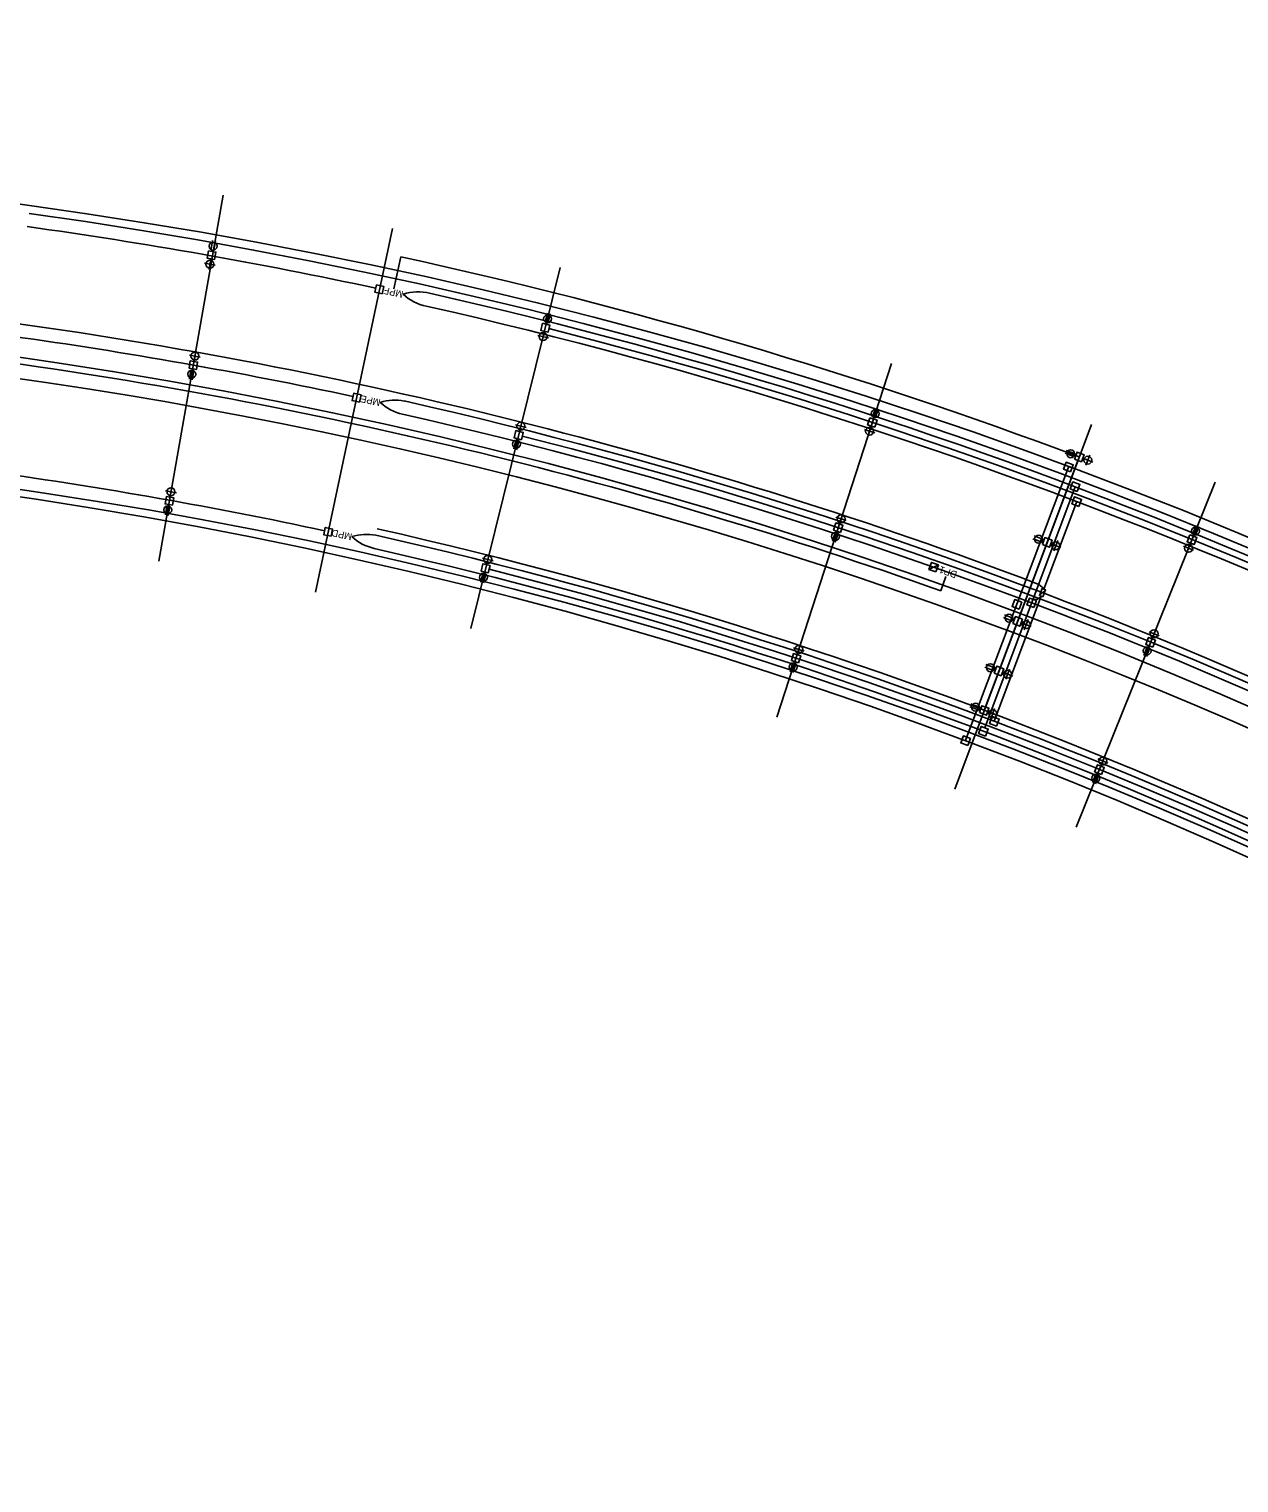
# Model space of a CAD drawing. Extents: x 928165 to 929015, y 635755 to 636543.
# Drawn here: x 928372.8 to 928555.1, y 636320.8 to 636539.8 of the extents above; entities that cross this region are included whole.
import ezdxf

# ---------------------------------------------------------------- set-up
doc = ezdxf.new("R2010")
doc.units = 0
for name, color, linetype in [('AdhocPoint_dp', 7, 'Continuous'), ('ScratchEle_dp', 7, 'Continuous'), ('TextMisc', 7, 'Continuous'), ('TextShtNo', 7, 'Continuous')]:
    doc.layers.add(name, color=color, linetype=linetype)

msp = doc.modelspace()

# ---------------------------------------------------------------- linework, layer by layer
at = {"layer": 'AdhocPoint_dp'}
for p, q in [((928509.78, 636459.1), (928508.35, 636458.42)), ((928508.35, 636458.42), (928509.78, 636459.1)), ((928525.92, 636455.33), (928525, 636454.48))]:
    msp.add_line(p, q, dxfattribs=at)
for points in [[(928399.81, 636506.4), (928400.92, 636506.21), (928400.73, 636505.1), (928399.62, 636505.29)], [(928425.99, 636499.92), (928424.89, 636500.17), (928425.14, 636501.26), (928426.23, 636501.02)], [(928450.14, 636495.5), (928451.23, 636495.23), (928450.96, 636494.14), (928449.87, 636494.41)], [(928397.99, 636488.54), (928396.88, 636488.74), (928397.07, 636489.84), (928398.18, 636489.65)], [(928422.54, 636483.62), (928421.44, 636483.86), (928421.69, 636484.96), (928422.79, 636484.71)], [(928499.46, 636481.27), (928500.53, 636480.92), (928500.19, 636479.85), (928499.11, 636480.2)], [(928446.95, 636477.96), (928445.86, 636478.23), (928446.13, 636479.33), (928447.22, 636479.05)], [(928529.69, 636473.11), (928528.63, 636473.51), (928529.03, 636474.56), (928530.08, 636474.17)], [(928530.27, 636475.03), (928530.66, 636476.08), (928531.72, 636475.68), (928531.32, 636474.63)], [(928530.7, 636470.14), (928529.65, 636470.54), (928530.05, 636471.59), (928531.1, 636471.19)], [(928394.38, 636468.1), (928393.27, 636468.29), (928393.46, 636469.4), (928394.57, 636469.21)], [(928530.94, 636467.91), (928529.88, 636468.31), (928530.28, 636469.36), (928531.34, 636468.96)], [(928418.27, 636463.4), (928417.17, 636463.64), (928417.41, 636464.74), (928418.51, 636464.5)], [(928495.05, 636463.99), (928493.98, 636464.34), (928494.33, 636465.41), (928495.4, 636465.06)], [(928547.67, 636463.63), (928548.71, 636463.21), (928548.29, 636462.16), (928547.25, 636462.58)], [(928525.44, 636462.15), (928525.83, 636463.2), (928526.89, 636462.81), (928526.49, 636461.75)], [(928441.97, 636457.9), (928440.88, 636458.17), (928441.15, 636459.27), (928442.24, 636459)], [(928509.41, 636458.04), (928508.35, 636458.42), (928508.72, 636459.48), (928509.78, 636459.1)], [(928525.52, 636454.28), (928525, 636454.48), (928525.39, 636455.53), (928525.92, 636455.33)], [(928521.92, 636452.43), (928520.87, 636452.83), (928521.27, 636453.88), (928522.32, 636453.48)], [(928524.15, 636452.66), (928523.1, 636453.06), (928523.49, 636454.11), (928524.55, 636453.71)], [(928520.98, 636450.25), (928521.37, 636451.31), (928522.43, 636450.91), (928522.03, 636449.86)], [(928542.06, 636446.7), (928541.02, 636447.12), (928541.44, 636448.17), (928542.48, 636447.75)], [(928488.69, 636444.33), (928487.62, 636444.68), (928487.96, 636445.75), (928489.03, 636445.4)], [(928518.18, 636442.8), (928518.58, 636443.85), (928519.63, 636443.46), (928519.23, 636442.4)], [(928515.95, 636436.84), (928516.34, 636437.89), (928517.39, 636437.5), (928517, 636436.45)], [(928518.53, 636434.83), (928517.48, 636435.23), (928517.87, 636436.28), (928518.93, 636435.88)], [(928514.2, 636431.88), (928513.15, 636432.28), (928513.55, 636433.33), (928514.6, 636432.93)], [(928516.89, 636433.31), (928515.84, 636433.71), (928516.24, 636434.76), (928517.29, 636434.36)], [(928534.34, 636427.53), (928533.3, 636427.95), (928533.72, 636429), (928534.76, 636428.58)]]:
    msp.add_lwpolyline(points, close=True, dxfattribs=at)
msp.add_lwpolyline([(928509.78, 636459.1), (928508.72, 636459.48), (928508.35, 636458.42)], dxfattribs=at)
at = {"layer": 'ScratchEle_dp'}
for p, q in [((928372.83, 636513.24), (928182.32, 636539.81)), ((928427.73, 636500.66), (928428.78, 636505.5)), ((928530.8, 636474.83), (928516.67, 636437.17)), ((928513.8, 636432.54), (928529.36, 636473.84)), ((928516.76, 636434.56), (928530.38, 636470.86)), ((928525.66, 636455.43), (928530.61, 636468.64)), ((928510.9, 636457.33), (928510.14, 636455.2)), ((928518.2, 636435.56), (928525.26, 636454.38))]:
    msp.add_line(p, q, dxfattribs=at)
for centre, radius, start, end in [((928272.36, 635783.24), 736.87, 358.73269, 82.16413), ((928270.99, 635782.23), 734.87, 77.90081, 82.06007), ((928270.99, 635782.23), 740.29, 69.43836, 77.69327), ((928431.37, 636493), 7.23, 75.9231, 107.8874), ((928434.09, 636505.15), 7.23, 226.9193, 258.1863), ((928270.99, 635782.23), 735.87, 38.12207, 77.2713), ((928270.99, 635782.23), 733.87, 38.11098, 77.27781), ((928270.99, 635782.23), 720.2, 69.39705, 82.06007), ((928270.99, 635782.23), 734.87, 359.8573, 75.81316), ((928270.99, 635782.23), 718.2, 77.89707, 82.06007), ((928269.66, 635781.44), 716.2, 358.82492, 82.06007), ((928270.99, 635782.23), 714.2, 70.43646, 82.06007), ((928427.92, 636476.69), 7.23, 78.9065, 107.8874), ((928430.63, 636488.85), 7.23, 226.9193, 257.2693), ((928270.99, 635782.23), 719.2, 38.12193, 77.28356), ((928270.99, 635782.23), 717.2, 38.11087, 77.26942), ((928270.99, 635782.23), 718.2, 359.85255, 75.80738), ((928270.99, 635782.23), 697.53, 77.89219, 82.06007), ((928269.58, 635781.3), 695.53, 358.77784, 82.06007), ((928423.65, 636456.47), 7.23, 79.2072, 107.8874), ((928270.99, 635782.23), 698.53, 38.11225, 77.26303), ((928426.37, 636468.63), 7.23, 226.9193, 257.2455), ((928270.99, 635782.23), 696.53, 38.11231, 77.24555), ((928270.99, 635782.23), 697.53, 359.84634, 75.79974), ((928523.47, 636453.82), 2.72, 36.3732, 69.397), ((928524.32, 636455), 1.13, 254.6207, 326.4923)]:
    msp.add_arc(centre, radius, start, end, dxfattribs=at)
at = {"layer": 'TextMisc'}
for p, q in [((928392.35, 636459.65), (928402.02, 636514.81)), ((928415.92, 636455), (928427.51, 636509.79)), ((928439.31, 636449.53), (928452.8, 636503.88)), ((928485.45, 636436.17), (928502.7, 636489.44)), ((928512.23, 636425.34), (928532.84, 636480.27)), ((928530.55, 636419.61), (928551.47, 636471.56)), ((928524.35, 636457.64), (928527.98, 636467.31)), ((928517.09, 636438.29), (928520.72, 636447.96))]:
    msp.add_line(p, q, dxfattribs=at)
for radius, start, end in [(736.87, 0.06217, 82.06007), (712.03, 51.1053, 82.06007), (695.53, 0.06217, 82.06007), (699.53, 38.11225, 77.26303)]:
    msp.add_arc((928270.99, 635782.23), radius, start, end, dxfattribs=at)
at = {"layer": 'TextShtNo'}
for p, q in [((928400.43, 636507.96), (928400.19, 636506.61)), ((928400.87, 636507.89), (928400.63, 636506.53)), ((928400.17, 636505.2), (928399.89, 636503.58)), ((928400.37, 636506.31), (928400.41, 636506.53)), ((928399.22, 636504.53), (928400.84, 636504.25)), ((928450.87, 636497.01), (928450.53, 636495.68)), ((928451.3, 636496.91), (928450.97, 636495.57)), ((928450.42, 636494.27), (928450.02, 636492.68)), ((928450.69, 636495.37), (928450.74, 636495.58)), ((928449.42, 636493.67), (928451.02, 636493.28)), ((928398.58, 636490.41), (928396.96, 636490.7)), ((928397.63, 636489.75), (928397.91, 636491.37)), ((928396.93, 636487.06), (928397.17, 636488.41)), ((928397.37, 636486.98), (928397.61, 636488.33)), ((928397.43, 636488.64), (928397.4, 636488.42)), ((928500.29, 636482.73), (928499.87, 636481.42)), ((928500, 636481.09), (928500.07, 636481.31)), ((928500.72, 636482.59), (928500.29, 636481.28)), ((928447.67, 636479.79), (928446.07, 636480.19)), ((928446.67, 636479.19), (928447.07, 636480.78)), ((928498.62, 636479.49), (928500.18, 636478.99)), ((928499.65, 636480.02), (928499.14, 636478.46)), ((928445.79, 636476.56), (928446.12, 636477.89)), ((928446.23, 636476.45), (928446.56, 636477.78)), ((928446.4, 636478.1), (928446.35, 636477.88)), ((928528.85, 636475.92), (928530.14, 636475.44)), ((928529.01, 636476.34), (928530.29, 636475.86)), ((928530.47, 636475.55), (928530.26, 636475.63)), ((928531.52, 636475.16), (928533.06, 636474.58)), ((928532, 636474.1), (928532.58, 636475.64)), ((928394.97, 636469.97), (928393.35, 636470.25)), ((928394.02, 636469.3), (928394.3, 636470.92)), ((928393.32, 636466.62), (928393.55, 636467.97)), ((928393.82, 636468.2), (928393.78, 636467.97)), ((928393.76, 636466.54), (928394, 636467.89)), ((928495.9, 636465.77), (928494.33, 636466.27)), ((928494.86, 636465.24), (928495.37, 636466.8)), ((928493.8, 636462.67), (928494.22, 636463.98)), ((928494.22, 636462.53), (928494.65, 636463.84)), ((928494.52, 636464.17), (928494.45, 636463.95)), ((928548.59, 636465.03), (928548.08, 636463.75)), ((928548.19, 636463.42), (928548.27, 636463.63)), ((928549.01, 636464.86), (928548.5, 636463.58)), ((928524.02, 636463.04), (928525.31, 636462.56)), ((928524.18, 636463.46), (928525.46, 636462.98)), ((928525.64, 636462.67), (928525.43, 636462.75)), ((928526.69, 636462.28), (928528.23, 636461.7)), ((928527.17, 636461.22), (928527.75, 636462.76)), ((928546.7, 636461.92), (928548.22, 636461.3)), ((928547.77, 636462.37), (928547.15, 636460.85)), ((928442.69, 636459.73), (928441.09, 636460.13)), ((928441.7, 636459.13), (928442.09, 636460.73)), ((928440.82, 636456.5), (928441.14, 636457.83)), ((928441.25, 636456.39), (928441.58, 636457.72)), ((928441.43, 636458.04), (928441.37, 636457.82)), ((928519.56, 636451.15), (928520.84, 636450.67)), ((928519.72, 636451.57), (928521, 636451.09)), ((928521.17, 636450.78), (928520.96, 636450.86)), ((928522.71, 636449.33), (928523.29, 636450.87)), ((928522.23, 636450.39), (928523.77, 636449.81)), ((928543.03, 636448.41), (928541.51, 636449.03)), ((928541.96, 636447.96), (928542.58, 636449.48)), ((928489.53, 636446.1), (928487.97, 636446.61)), ((928488.5, 636445.58), (928489, 636447.14)), ((928540.72, 636445.47), (928541.23, 636446.75)), ((928541.14, 636445.31), (928541.65, 636446.58)), ((928541.54, 636446.91), (928541.46, 636446.71)), ((928487.43, 636443.01), (928487.85, 636444.32)), ((928487.86, 636442.87), (928488.28, 636444.18)), ((928488.15, 636444.5), (928488.08, 636444.29)), ((928516.92, 636444.11), (928518.2, 636443.63)), ((928516.76, 636443.69), (928518.05, 636443.21)), ((928518.38, 636443.32), (928518.17, 636443.4)), ((928519.43, 636442.93), (928520.97, 636442.35)), ((928519.91, 636441.87), (928520.49, 636443.41)), ((928514.53, 636437.73), (928515.81, 636437.25)), ((928514.68, 636438.16), (928515.97, 636437.67)), ((928516.14, 636437.37), (928515.93, 636437.45)), ((928517.68, 636435.91), (928518.25, 636437.45)), ((928517.2, 636436.97), (928518.73, 636436.4)), ((928535.31, 636429.24), (928533.79, 636429.86)), ((928534.24, 636428.79), (928534.85, 636430.31)), ((928533, 636426.3), (928533.51, 636427.58)), ((928533.42, 636426.14), (928533.93, 636427.41)), ((928533.82, 636427.74), (928533.74, 636427.53))]:
    msp.add_line(p, q, dxfattribs=at)
for centre in [(928400.51, 636507.11), (928400.03, 636504.39), (928450.89, 636496.16), (928450.22, 636493.48), (928397.77, 636490.56), (928397.29, 636487.83), (928500.25, 636481.88), (928446.87, 636479.99), (928499.4, 636479.24), (928446.2, 636477.3), (928529.7, 636475.84), (928532.29, 636474.87), (928394.16, 636470.11), (928393.68, 636467.39), (928495.12, 636466.02), (928494.26, 636463.39), (928524.87, 636462.96), (928548.5, 636464.18), (928527.46, 636461.99), (928547.46, 636461.61), (928441.89, 636459.93), (928441.23, 636457.24), (928520.41, 636451.07), (928523, 636450.1), (928542.27, 636448.72), (928488.75, 636446.36), (928541.23, 636446.15), (928487.9, 636443.72), (928517.61, 636443.61), (928520.2, 636442.64), (928515.37, 636437.66), (928517.97, 636436.68), (928534.55, 636429.55), (928533.51, 636426.98)]:
    msp.add_circle(centre, 0.597, dxfattribs=at)

# ---------------------------------------------------------------- texts
at = {"layer": 'AdhocPoint_dp'}
msp.add_text('DP1', height=1.05, rotation=160.5, dxfattribs=at).set_placement((928512.68, 636458.04))
at = {"layer": 'TextShtNo'}
for s, p in [('MPF', (928429.24, 636500.33)), ('MPE', (928425.8, 636484.02)), ('MPD', (928421.52, 636463.81))]:
    msp.add_text(s, height=1.05, rotation=167.6601, dxfattribs=at).set_placement(p)

doc.saveas('drawing.dxf')
